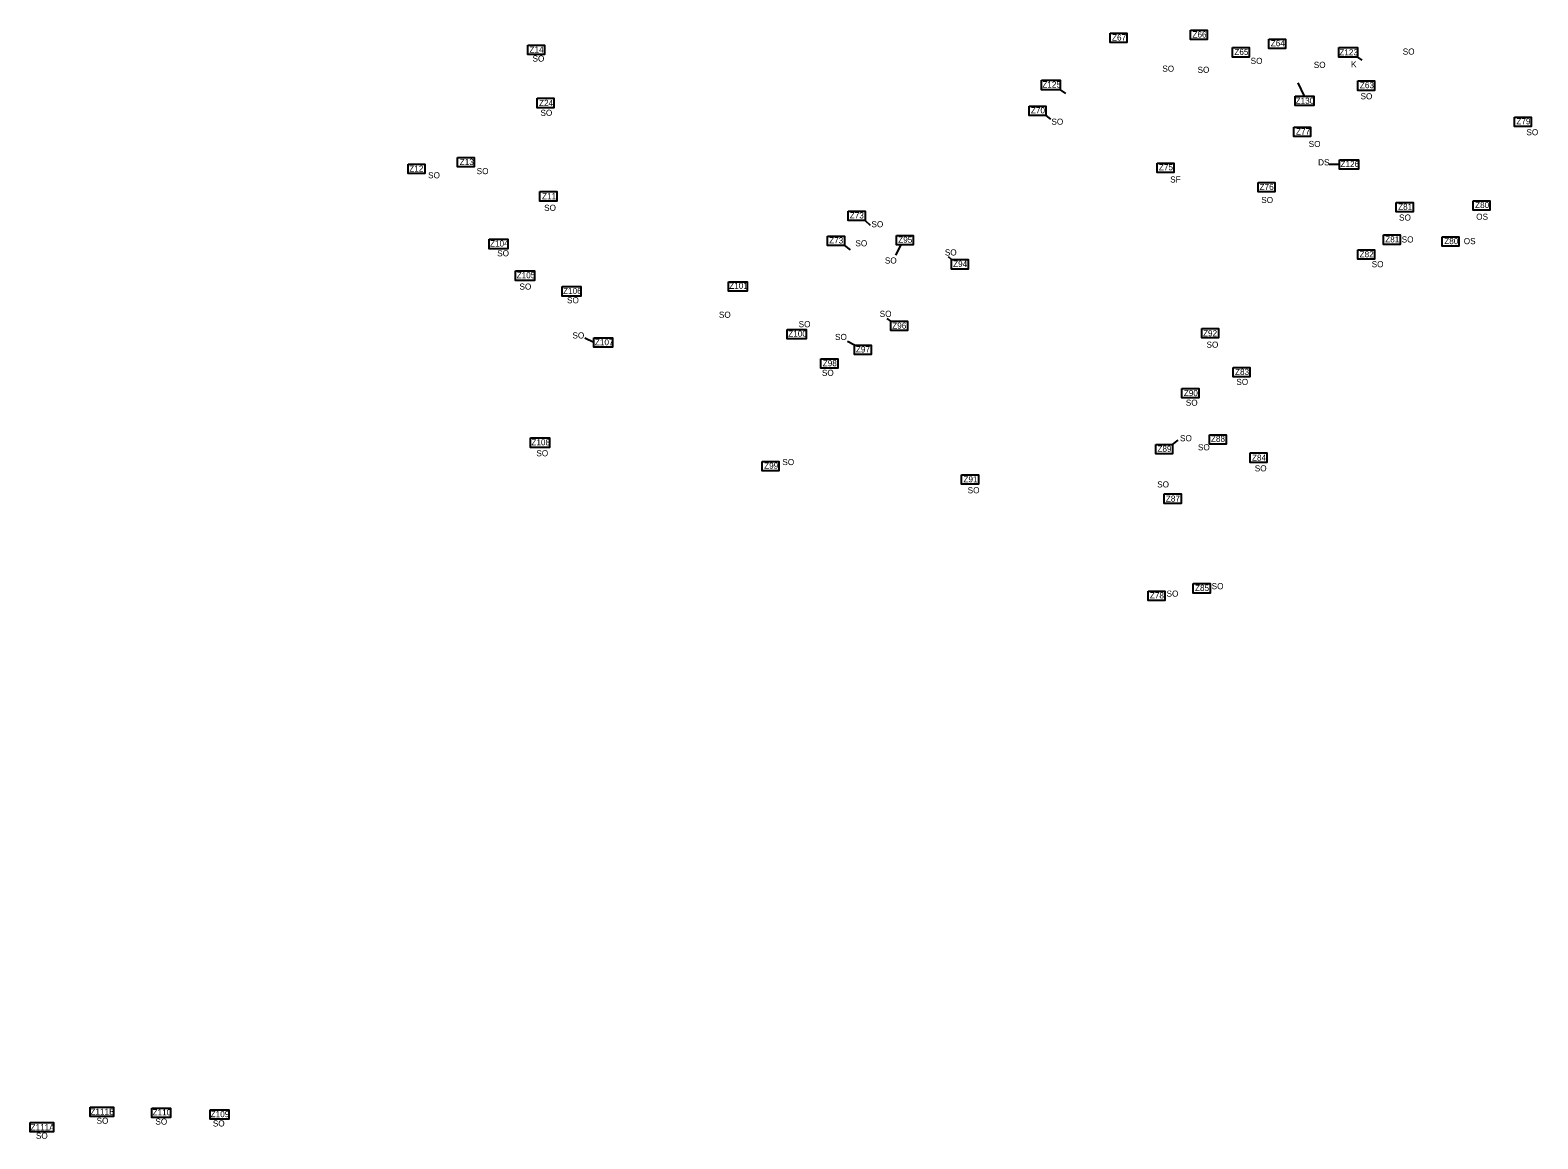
# Model space of a CAD drawing. Extents: x -443485 to -433023, y -1133480 to -1129775.
# Drawn here: x -443485 to -441021, y -1133480 to -1131668 of the extents above; entities that cross this region are included whole.
import ezdxf

# ---------------------------------------------------------------- set-up
doc = ezdxf.new("R2010")
doc.units = 0
for name, color, linetype in [('Vrstva 3', 7, 'Continuous'), ('Vrstva 4', 7, 'Continuous'), ('Vrstva 8', 7, 'Continuous')]:
    doc.layers.add(name, color=color, linetype=linetype)

msp = doc.modelspace()

# ---------------------------------------------------------------- linework, layer by layer
at = {"layer": 'Vrstva 3'}
for p, q in [((-441824.8, -1131807.6), (-441817.5, -1131813.7)), ((-442120.5, -1131979), (-442112, -1131986.9)), ((-442154.2, -1132019.9), (-442145, -1132026.9)), ((-442061.8, -1132018.8), (-442070.5, -1132035.8)), ((-441979.2, -1132043), (-441984, -1132038.5)), ((-442078.2, -1132143.6), (-442084.5, -1132139.3)), ((-442563.8, -1132178.3), (-442578.2, -1132171.1)), ((-442137.9, -1132182.9), (-442149.2, -1132176.8)), ((-441618.1, -1132344.9), (-441608.8, -1132338.2))]:
    msp.add_line(p, q, dxfattribs=at)
for points in [[(-441719.9, -1131672.7), (-441692.5, -1131672.7), (-441692.5, -1131688.1), (-441719.9, -1131688.1)], [(-441588.7, -1131668), (-441561.3, -1131668), (-441561.3, -1131683.4), (-441588.7, -1131683.4)], [(-442671.7, -1131692.6), (-442644.4, -1131692.6), (-442644.4, -1131708), (-442671.7, -1131708)], [(-441520.2, -1131696.6), (-441492.8, -1131696.6), (-441492.8, -1131712), (-441520.2, -1131712)], [(-441460.9, -1131682.5), (-441433.5, -1131682.5), (-441433.5, -1131697.9), (-441460.9, -1131697.9)], [(-441315.3, -1131751.1), (-441287.9, -1131751.1), (-441287.9, -1131766.5), (-441315.3, -1131766.5)], [(-442656.4, -1131779.4), (-442629, -1131779.4), (-442629, -1131794.8), (-442656.4, -1131794.8)], [(-441852.1, -1131792.2), (-441824.8, -1131792.2), (-441824.8, -1131807.6), (-441852.1, -1131807.6)], [(-441419.8, -1131826.6), (-441392.4, -1131826.6), (-441392.4, -1131842), (-441419.8, -1131842)], [(-441059.4, -1131810.2), (-441032.1, -1131810.2), (-441032.1, -1131825.6), (-441059.4, -1131825.6)], [(-442786.3, -1131876), (-442759, -1131876), (-442759, -1131891.4), (-442786.3, -1131891.4)], [(-442867, -1131887), (-442839.6, -1131887), (-442839.6, -1131902.4), (-442867, -1131902.4)], [(-441643.3, -1131885.3), (-441615.9, -1131885.3), (-441615.9, -1131900.7), (-441643.3, -1131900.7)], [(-441478.3, -1131917), (-441450.9, -1131917), (-441450.9, -1131932.4), (-441478.3, -1131932.4)], [(-442651.8, -1131931.9), (-442624.4, -1131931.9), (-442624.4, -1131947.3), (-442651.8, -1131947.3)], [(-441252.4, -1131949.4), (-441225, -1131949.4), (-441225, -1131964.8), (-441252.4, -1131964.8)], [(-441126.7, -1131946.9), (-441099.4, -1131946.9), (-441099.4, -1131962.3), (-441126.7, -1131962.3)], [(-442147.8, -1131963.6), (-442120.5, -1131963.6), (-442120.5, -1131979), (-442147.8, -1131979)], [(-442734.8, -1132009.7), (-442704, -1132009.7), (-442704, -1132025.1), (-442734.8, -1132025.1)], [(-442181.6, -1132004.5), (-442154.2, -1132004.5), (-442154.2, -1132019.9), (-442181.6, -1132019.9)], [(-442069.1, -1132003.4), (-442041.7, -1132003.4), (-442041.7, -1132018.8), (-442069.1, -1132018.8)], [(-441315.4, -1132026.8), (-441288, -1132026.8), (-441288, -1132042.2), (-441315.4, -1132042.2)], [(-441273.5, -1132002.7), (-441246.1, -1132002.7), (-441246.1, -1132018.1), (-441273.5, -1132018.1)], [(-441177.4, -1132005.6), (-441150, -1132005.6), (-441150, -1132021), (-441177.4, -1132021)], [(-441979.2, -1132043), (-441951.8, -1132043), (-441951.8, -1132058.4), (-441979.2, -1132058.4)], [(-442691.5, -1132061.4), (-442660.7, -1132061.4), (-442660.7, -1132076.8), (-442691.5, -1132076.8)], [(-442615.4, -1132087.1), (-442584.7, -1132087.1), (-442584.7, -1132102.5), (-442615.4, -1132102.5)], [(-442343.7, -1132079), (-442312.9, -1132079), (-442312.9, -1132094.4), (-442343.7, -1132094.4)], [(-442078.2, -1132143.6), (-442050.9, -1132143.6), (-442050.9, -1132159), (-442078.2, -1132159)], [(-442563.8, -1132170.6), (-442533.1, -1132170.6), (-442533.1, -1132186), (-442563.8, -1132186)], [(-442247.5, -1132157.2), (-442216.7, -1132157.2), (-442216.7, -1132172.6), (-442247.5, -1132172.6)], [(-441570.4, -1132155.6), (-441543.1, -1132155.6), (-441543.1, -1132171), (-441570.4, -1132171)], [(-442137.9, -1132182.9), (-442110.5, -1132182.9), (-442110.5, -1132198.2), (-442137.9, -1132198.2)], [(-442192.5, -1132204.9), (-442165.1, -1132204.9), (-442165.1, -1132220.3), (-442192.5, -1132220.3)], [(-441518.9, -1132219.3), (-441491.5, -1132219.3), (-441491.5, -1132234.7), (-441518.9, -1132234.7)], [(-441602.6, -1132253.6), (-441575.2, -1132253.6), (-441575.2, -1132269), (-441602.6, -1132269)], [(-442667.1, -1132334.4), (-442636.3, -1132334.4), (-442636.3, -1132349.8), (-442667.1, -1132349.8)], [(-441645.5, -1132344.9), (-441618.1, -1132344.9), (-441618.1, -1132360.3), (-441645.5, -1132360.3)], [(-441557.5, -1132329), (-441530.2, -1132329), (-441530.2, -1132344.4), (-441557.5, -1132344.4)], [(-441491.3, -1132358.9), (-441463.9, -1132358.9), (-441463.9, -1132374.3), (-441491.3, -1132374.3)], [(-442288.6, -1132372.9), (-442261.2, -1132372.9), (-442261.2, -1132388.3), (-442288.6, -1132388.3)], [(-441962.6, -1132394.5), (-441935.3, -1132394.5), (-441935.3, -1132409.9), (-441962.6, -1132409.9)], [(-441631.5, -1132425.8), (-441604.1, -1132425.8), (-441604.1, -1132441.2), (-441631.5, -1132441.2)], [(-441657.9, -1132584.5), (-441630.5, -1132584.5), (-441630.5, -1132599.9), (-441657.9, -1132599.9)], [(-441584.1, -1132572.3), (-441556.7, -1132572.3), (-441556.7, -1132587.7), (-441584.1, -1132587.7)], [(-443387, -1133427.6), (-443348.5, -1133427.6), (-443348.5, -1133443), (-443387, -1133443)], [(-443286.1, -1133429.5), (-443255.3, -1133429.5), (-443255.3, -1133444.9), (-443286.1, -1133444.9)], [(-443484.8, -1133452.9), (-443446.4, -1133452.9), (-443446.4, -1133468.3), (-443484.8, -1133468.3)], [(-443190.7, -1133432.2), (-443160, -1133432.2), (-443160, -1133447.6), (-443190.7, -1133447.6)]]:
    msp.add_lwpolyline(points, close=True, dxfattribs=at)
at = {"layer": 'Vrstva 8'}
for p, q in [((-441315.6, -1131712), (-441308.9, -1131717.3)), ((-441402.4, -1131775.9), (-441412.9, -1131754.3)), ((-441801.4, -1131765.3), (-441793.1, -1131771.6)), ((-441345, -1131887.4), (-441361.9, -1131887.4))]:
    msp.add_line(p, q, dxfattribs=at)
for points in [[(-441346.4, -1131696.6), (-441315.6, -1131696.6), (-441315.6, -1131712), (-441346.4, -1131712)], [(-441832.2, -1131749.9), (-441801.4, -1131749.9), (-441801.4, -1131765.3), (-441832.2, -1131765.3)], [(-441417.8, -1131775.9), (-441387.1, -1131775.9), (-441387.1, -1131791.3), (-441417.8, -1131791.3)], [(-441345, -1131879.7), (-441314.2, -1131879.7), (-441314.2, -1131895.1), (-441345, -1131895.1)]]:
    msp.add_lwpolyline(points, close=True, dxfattribs=at)

# ---------------------------------------------------------------- texts
at = {"layer": 'Vrstva 3'}
for s, p in [('Z67', (-441716.9, -1131685)), ('Z66', (-441585.5, -1131680.1)), ('Z14', (-442668.9, -1131704.8)), ('Z65', (-441517, -1131708.6)), ('Z64', (-441457.5, -1131694.4)), ('Z63', (-441311.9, -1131762.9)), ('Z24', (-442653.2, -1131791.9)), ('Z70', (-441849.5, -1131804.1)), ('Z77', (-441416.3, -1131838.6)), ('Z79', (-441056.1, -1131821.9)), ('Z13', (-442782.8, -1131888.3)), ('Z12', (-442865.3, -1131899.3)), ('Z75', (-441640.3, -1131897)), ('Z76', (-441475.8, -1131929.2)), ('Z11', (-442648.3, -1131944.2)), ('Z81', (-441249.4, -1131961.6)), ('Z80', (-441123.6, -1131958.7)), ('Z73', (-442145.5, -1131975.7)), ('Z104', (-442733.3, -1132021.6)), ('Z73', (-442179.2, -1132016.6)), ('Z95', (-442066.3, -1132015.4)), ('Z81', (-441270.5, -1132014.9)), ('Z80', (-441174, -1132017.7)), ('Z94', (-441976.6, -1132054.9)), ('Z82', (-441312.3, -1132039.2)), ('Z105', (-442689.8, -1132073.4)), ('Z106', (-442614, -1132099.2)), ('Z101', (-442342.5, -1132090.7)), ('Z96', (-442076.1, -1132155.8)), ('Z107', (-442562, -1132182.9)), ('Z100', (-442246, -1132169)), ('Z92', (-441568.2, -1132168.2)), ('Z97', (-442135.5, -1132194.7)), ('Z98', (-442189.6, -1132217.2)), ('Z83', (-441515.9, -1132231.4)), ('Z90', (-441599.6, -1132266)), ('Z108', (-442665.7, -1132346.4)), ('Z89', (-441642.7, -1132357)), ('Z88', (-441555.3, -1132340.8)), ('Z84', (-441488.2, -1132371.5)), ('Z99', (-442285.4, -1132384.6)), ('Z91', (-441959.7, -1132406.9)), ('Z87', (-441628.9, -1132438.4)), ('Z78', (-441655.1, -1132596.5)), ('Z85', (-441581.3, -1132584.3)), ('Z111B', (-443386.3, -1133440.1)), ('Z110', (-443284.8, -1133441.2)), ('Z111A', (-443484.1, -1133465.5)), ('Z109', (-443189.9, -1133444.1))]:
    msp.add_text(s, height=10, dxfattribs=at).set_placement(p)
at = {"layer": 'Vrstva 4'}
for s, p in [('SO', (-441241.8, -1131708)), ('SO', (-442663.9, -1131719.4)), ('SO', (-441634.7, -1131735.9)), ('SO', (-441577.1, -1131737.8)), ('SO', (-441490.4, -1131723.2)), ('SO', (-441387.2, -1131729.7)), ('K', (-441326.3, -1131728.7)), ('SO', (-441310.8, -1131781)), ('SO', (-442650.9, -1131808.1)), ('SO', (-441815.9, -1131822.6)), ('SO', (-441039.7, -1131839.8)), ('SO', (-441395.5, -1131859)), ('DS', (-441380.1, -1131889)), ('SO', (-442834.5, -1131910.1)), ('SO', (-442755.1, -1131903.3)), ('SF', (-441621.9, -1131917)), ('SO', (-441473, -1131950.5)), ('SO', (-442644.9, -1131963.3)), ('SO', (-441247.8, -1131979.2)), ('OS', (-441121.8, -1131977.8)), ('SO', (-442110, -1131990.1)), ('SO', (-442136.2, -1132021.2)), ('SO', (-441990.1, -1132036.2)), ('SO', (-441243.5, -1132015)), ('OS', (-441142.1, -1132017.7)), ('SO', (-442721.6, -1132037.6)), ('SO', (-442088.1, -1132049.4)), ('SO', (-441292.5, -1132055.4)), ('SO', (-442685.2, -1132092)), ('SO', (-442607.5, -1132114.3)), ('SO', (-442359.3, -1132138)), ('SO', (-442229, -1132153.4)), ('SO', (-442096.5, -1132136.5)), ('SO', (-442598.6, -1132171.8)), ('SO', (-442169.5, -1132174.3)), ('SO', (-441562.5, -1132186.9)), ('SO', (-442191, -1132232.9)), ('SO', (-441513.7, -1132247.8)), ('SO', (-441596.3, -1132281.7)), ('SO', (-441605.7, -1132339.7)), ('SO', (-441576.5, -1132354.6)), ('SO', (-442657.6, -1132364.3)), ('SO', (-442255.6, -1132378.7)), ('SO', (-441483.6, -1132389)), ('SO', (-441952.8, -1132424.7)), ('SO', (-441643.1, -1132415.2)), ('SO', (-441627.8, -1132593.7)), ('SO', (-441554.1, -1132581.5)), ('SO', (-443376.3, -1133454.9)), ('SO', (-443280.1, -1133456.3)), ('SO', (-443186.3, -1133459.3)), ('SO', (-443475.4, -1133479.4))]:
    msp.add_text(s, height=10, dxfattribs=at).set_placement(p)
at = {"layer": 'Vrstva 8'}
for s, p in [('Z123', (-441345.4, -1131709.1)), ('Z125', (-441830.8, -1131761.9)), ('Z130', (-441416.9, -1131788.4)), ('Z126', (-441343.6, -1131891.7))]:
    msp.add_text(s, height=10, dxfattribs=at).set_placement(p)

doc.saveas('drawing.dxf')
